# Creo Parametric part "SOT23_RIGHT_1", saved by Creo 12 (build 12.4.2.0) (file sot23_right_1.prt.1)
Units: Custom; MM, KILOGRAM, SECS

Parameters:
  PTC_WM_ITERATION = "0"
  PTC_WM_VERSION = "-.0"
  PTC_WM_LIFECYCLE_STATE = "In Work"
  PTC_WM_LIFECYCLE = "MO_CADDocument"
  PTC_WM_CREATED_BY = "Maximilian Roepper (Z0017RMS: MO)"
  PTC_WM_CREATED_ON = "18-Sep-26 11:36:42 AM"
  PTC_WM_MODIFIED_BY = "Maximilian Roepper (Z0017RMS: MO)"
  PTC_WM_MODIFIED_ON = "18-Sep-26 11:36:46 AM"
  PDMLINKNUMBER = "PDM000071455230"
  PTC_WM_NAME = "sot23_right_1.prt"
  PTC_WM_NUMBER = "PDM000071455230"

Other parameters: WEIGHT, WEIGHT_FACTOR, WEIGHT_ADD, _MASS_TEMP, _DIFF_TEMP, MC_ERRORS, SUPPLIER

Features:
  1. coordinate system
  2. datum plane "PRT_YZ"
  3. datum plane "PRT_XY"
  4. datum plane "PRT_XZ"
  5. coordinate system
  6. datum axis
  7. datum axis
  8. datum axis
  9. coordinate system
  10. imported feature

Other named items: PRT, SIEMENS_MO, DRW_VIEW_ORG, PRT_X, PRT_Y, PRT_Z, CS0, ROUGH_GROB

Layers: 00_STD_CSYS-KSYS, 01_STD_PLANES-EBENEN, 02_STD_AXES-ACHSEN, 03_STD_CSYS-KSYS, 24_IMPORT_FEAT-IMPORT_KE

Surfaces: 8 plane, 2 cylinder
